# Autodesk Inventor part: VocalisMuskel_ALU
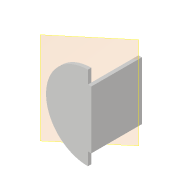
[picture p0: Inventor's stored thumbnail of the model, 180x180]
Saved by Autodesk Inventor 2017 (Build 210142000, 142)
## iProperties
Part Number: VocalisMuskel_ALU
Material: Generisch
Document SubType Name: Modeling
Designer: gabriel
Density: 1 g/cm^3
Appearance: Vorgabe
Author: gabriel
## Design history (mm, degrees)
sketch "Skizze1"
  geometry: L1 (0, 19.5)-(0, -19.5); A1 r 19.5 centre (0, 0) between (0, -19.5) and (0, 19.5); 1 further point
  constraints: 2 end point, 2 point on circle, 1 centre point, 1 coincident, 1 vertical
extrude "Extrusion1" new body sketch "Skizze1" distance "d0" = 1.6; taper "d1" = 0 deg
sketch "Skizze2"
  geometry: L1 (0, -8.5)-(0, 8.5); L2 (0, -19.5)-(0, 19.5) reference; A1 r 8.5 centre (0, 0) between (0, 8.5) and (0, -8.5); 2 further points
  constraints: 2 end point, 2 midpoint, 2 point on circle, 1 centre point, 1 coincident, 1 vertical
  dimensions: "d28" = 17 distance of L1.start L1.end
extrude "Extrusion2" join sketch "Skizze2" distance "d2" = 19; taper "d3" = 0 deg
workplane "Arbeitsebene1"
sketch "Skizze3"
  geometry: L1 (-1.5, 0)-(18.5, 0); L2 (18.5, 0)-(18.5, -15.513); L3 (18.5, -15.513)-(-1.5, -15.513); L4 (-1.5, -15.513)-(-1.5, 0); 1 further point
  constraints: 8 end point, 2 parallel, 1 horizontal, 1 perpendicular
extrude "Extrusion3" cut sketch "Skizze3" distance "d5" = 10; taper "d6" = 0 deg
sketch "Skizze5"
  geometry: L1 (0, -19.5)-(0, 19.5) reference; L2 (0, 8.5)-(0, -8.5); L3 (0, 27.3)-(0, -27.3) reference; L4 (-23.72, 0)-(5.82, 0) reference; L5 (0, 19.5)-(0, 8.5) reference; L6 (0, -8.5)-(0, -19.5) reference; L7 (0, 8.5)-(0, -8.5) reference; L8 (-1, 8.441)-(-1, -8.441); A1 r 8.5 centre (0, 0) between (0, 8.5) and (0, -8.5) reference; A2 r 19.5 centre (0, 0) between (0, 19.5) and (0, -19.5) reference; A3 r 8.5 centre (0, 0) between (0, 8.5) and (0, -8.5) reference; A4 r 8.5 centre (0, 0) between (0, 8.5) and (0, -8.5) reference; A5 r 8.5 centre (0, 0) between (0, 8.5) and (-1, 8.441); A6 r 8.5 centre (0, 0) between (-1, -8.441) and (0, -8.5); 1 further point
  constraints: 4 end point, 4 point on circle, 2 centre point, 1 coincident, 1 point on line, 1 symmetric about line, 1 vertical
  dimensions: "d26" = 17 distance of L2.start L2.end; "d29" = 1 distance between parallel lines of L1 L8
  node "Schnittkanten projizieren2"
sketch "Skizze6"
  geometry: L1 (46.8, 0)-(-7.8, 0) reference; L2 (19.5, -4.72)-(19.5, 28.32) reference; L3 (0, 0)-(39, 0) reference; L4 (6, 0)-(33, 0); L5 (33, 0)-(33, 23.6); L6 (33, 23.6)-(6, 23.6); L7 (6, 23.6)-(6, 0); 1 further point
  constraints: 8 end point, 2 parallel, 1 horizontal, 1 perpendicular, 1 point on line, 1 other
  dimensions: "d18" = 27 distance of L5.end L6.end; "d19" = 23.6 distance of L6.end L4.start
extrude "Extrusion6" join sketch "Skizze6" distance "d20" = 1.6; taper "d21" = 0 deg
extrude "Extrusion8" join sketch "Skizze5" distance "d30" = 22; taper "d31" = 0 deg
fillet "Rundung2" dims "d36" = 1
node "Volumenkörper1"
other parameters: "d15" = 50 deg
